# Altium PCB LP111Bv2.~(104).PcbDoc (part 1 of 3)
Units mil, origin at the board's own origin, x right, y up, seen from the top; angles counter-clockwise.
Board outline 3543.31 x 7480.32 mil, 4 copper layers (Top Layer, Signal Layer 1, Signal Layer 2, Bottom Layer), stack 40 mil thick; 284 components, 118 nets, 594 pads, 103 vias.
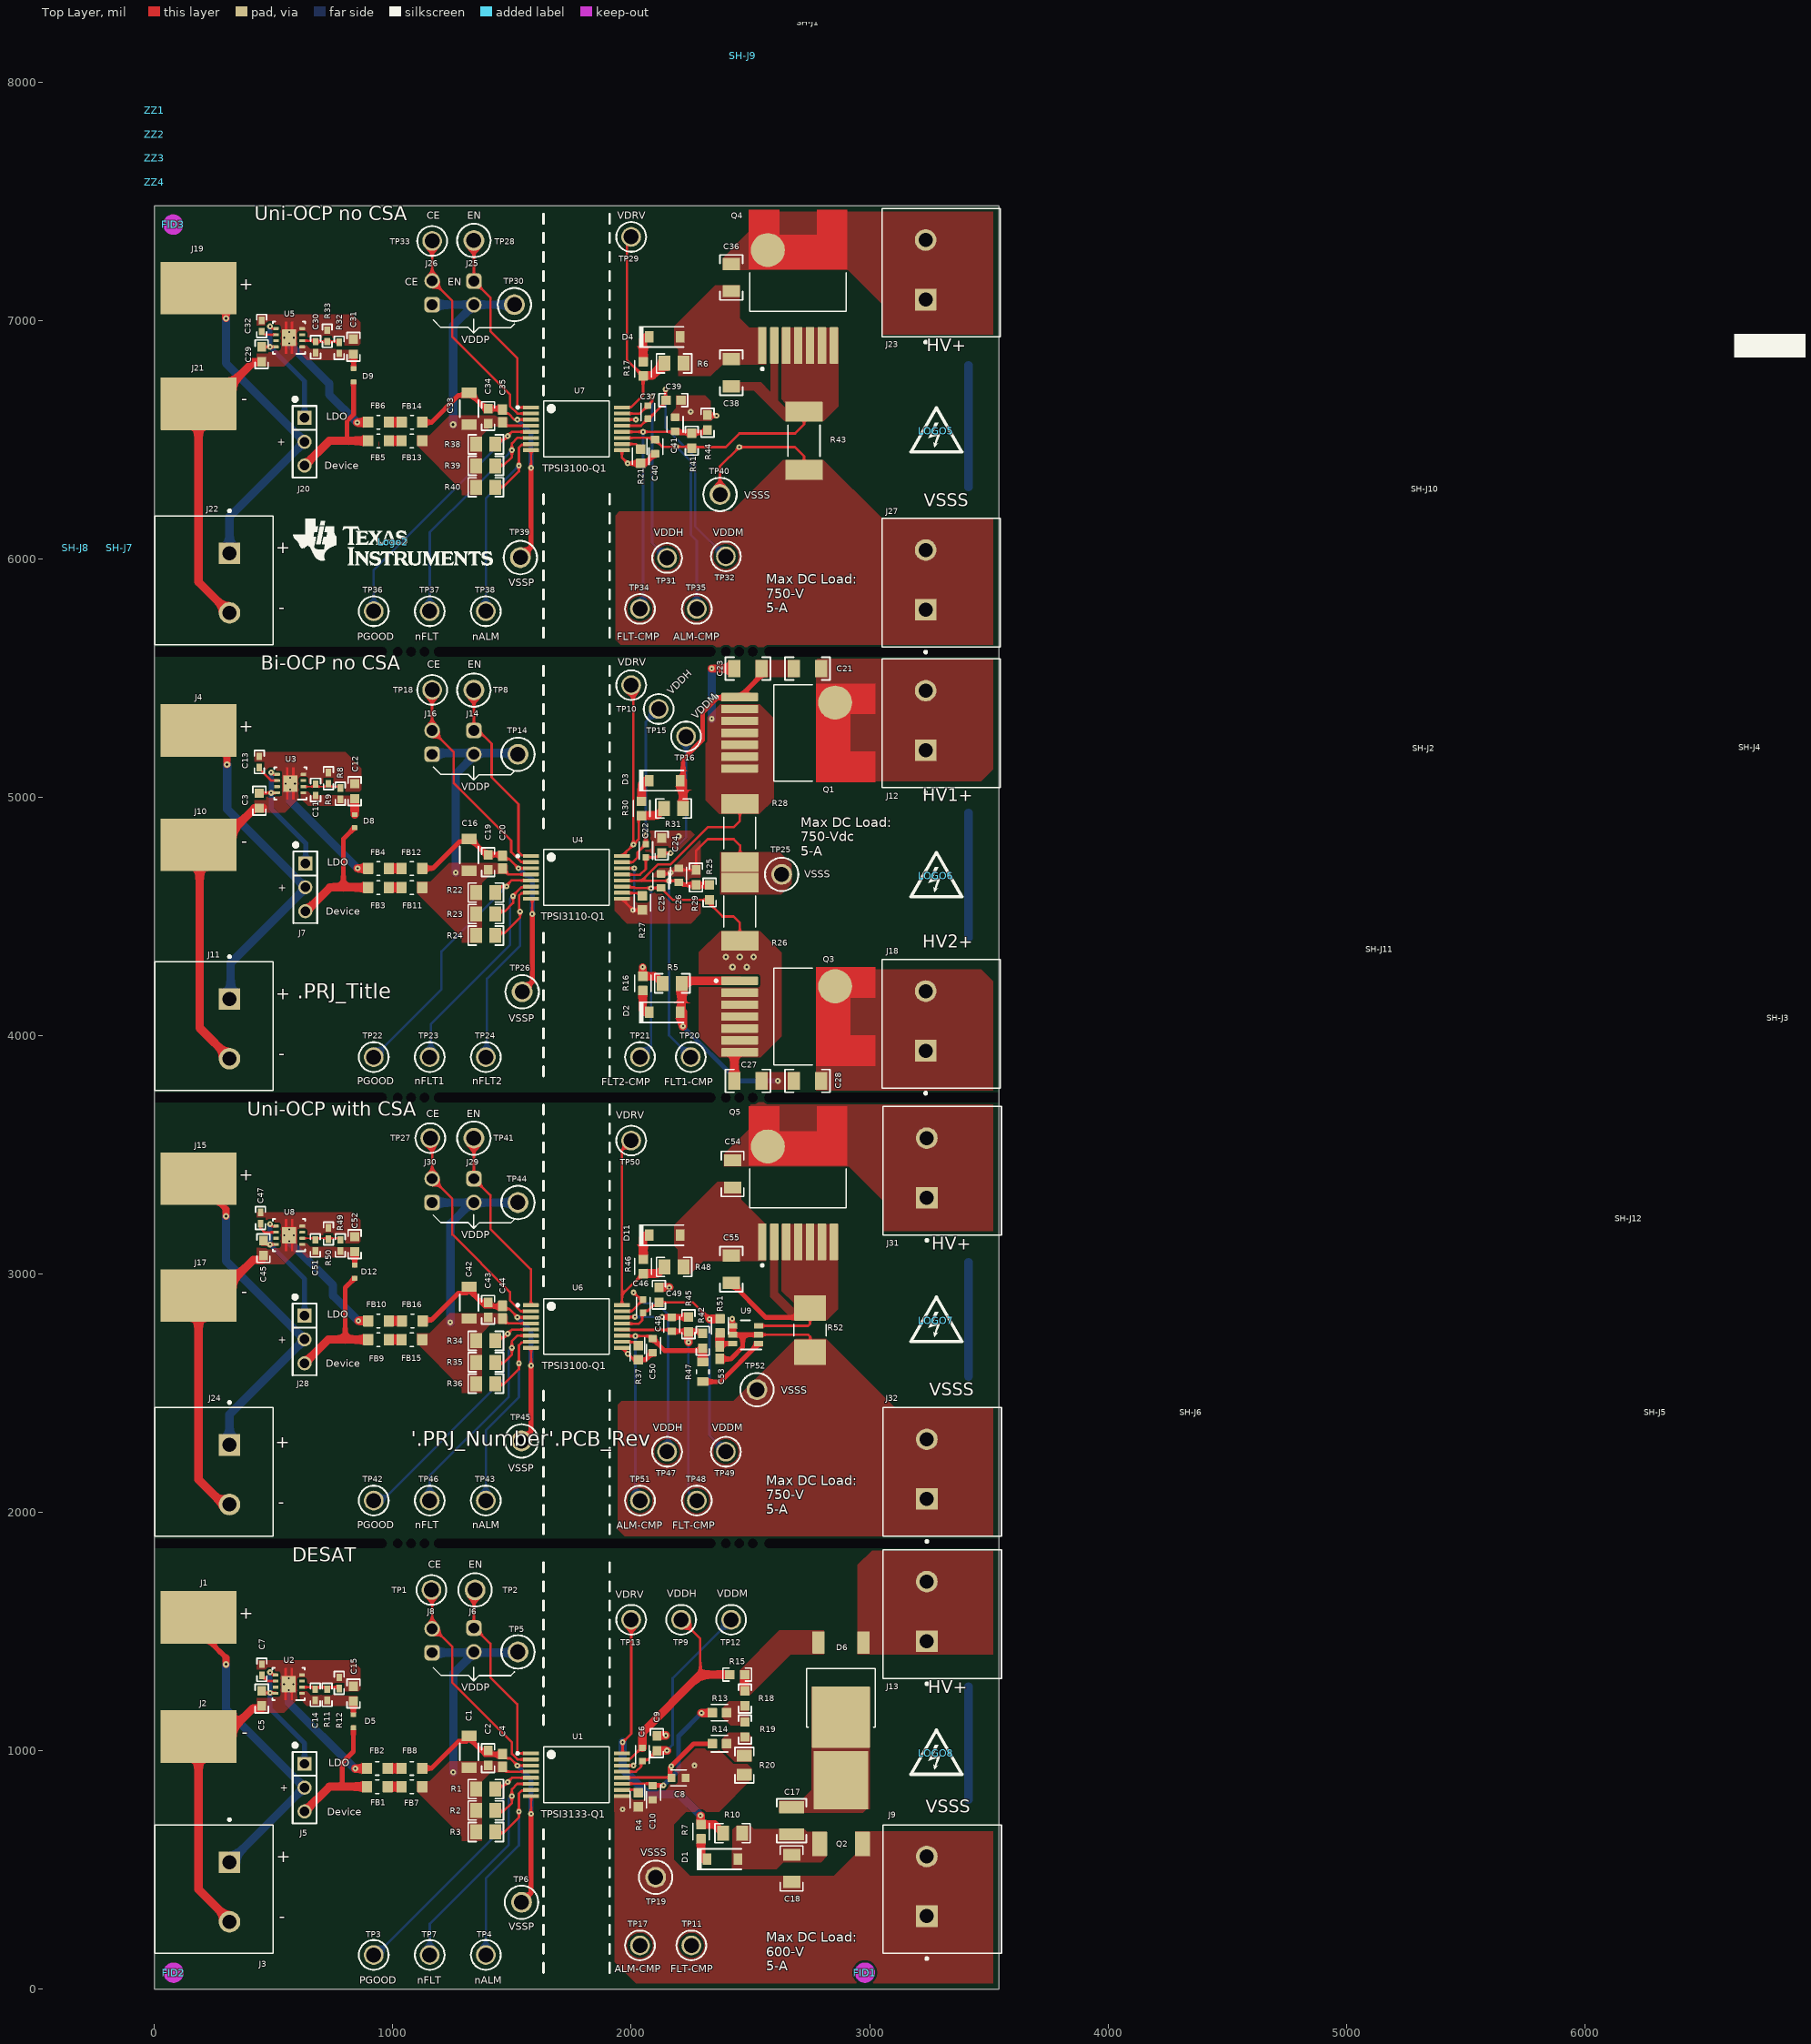
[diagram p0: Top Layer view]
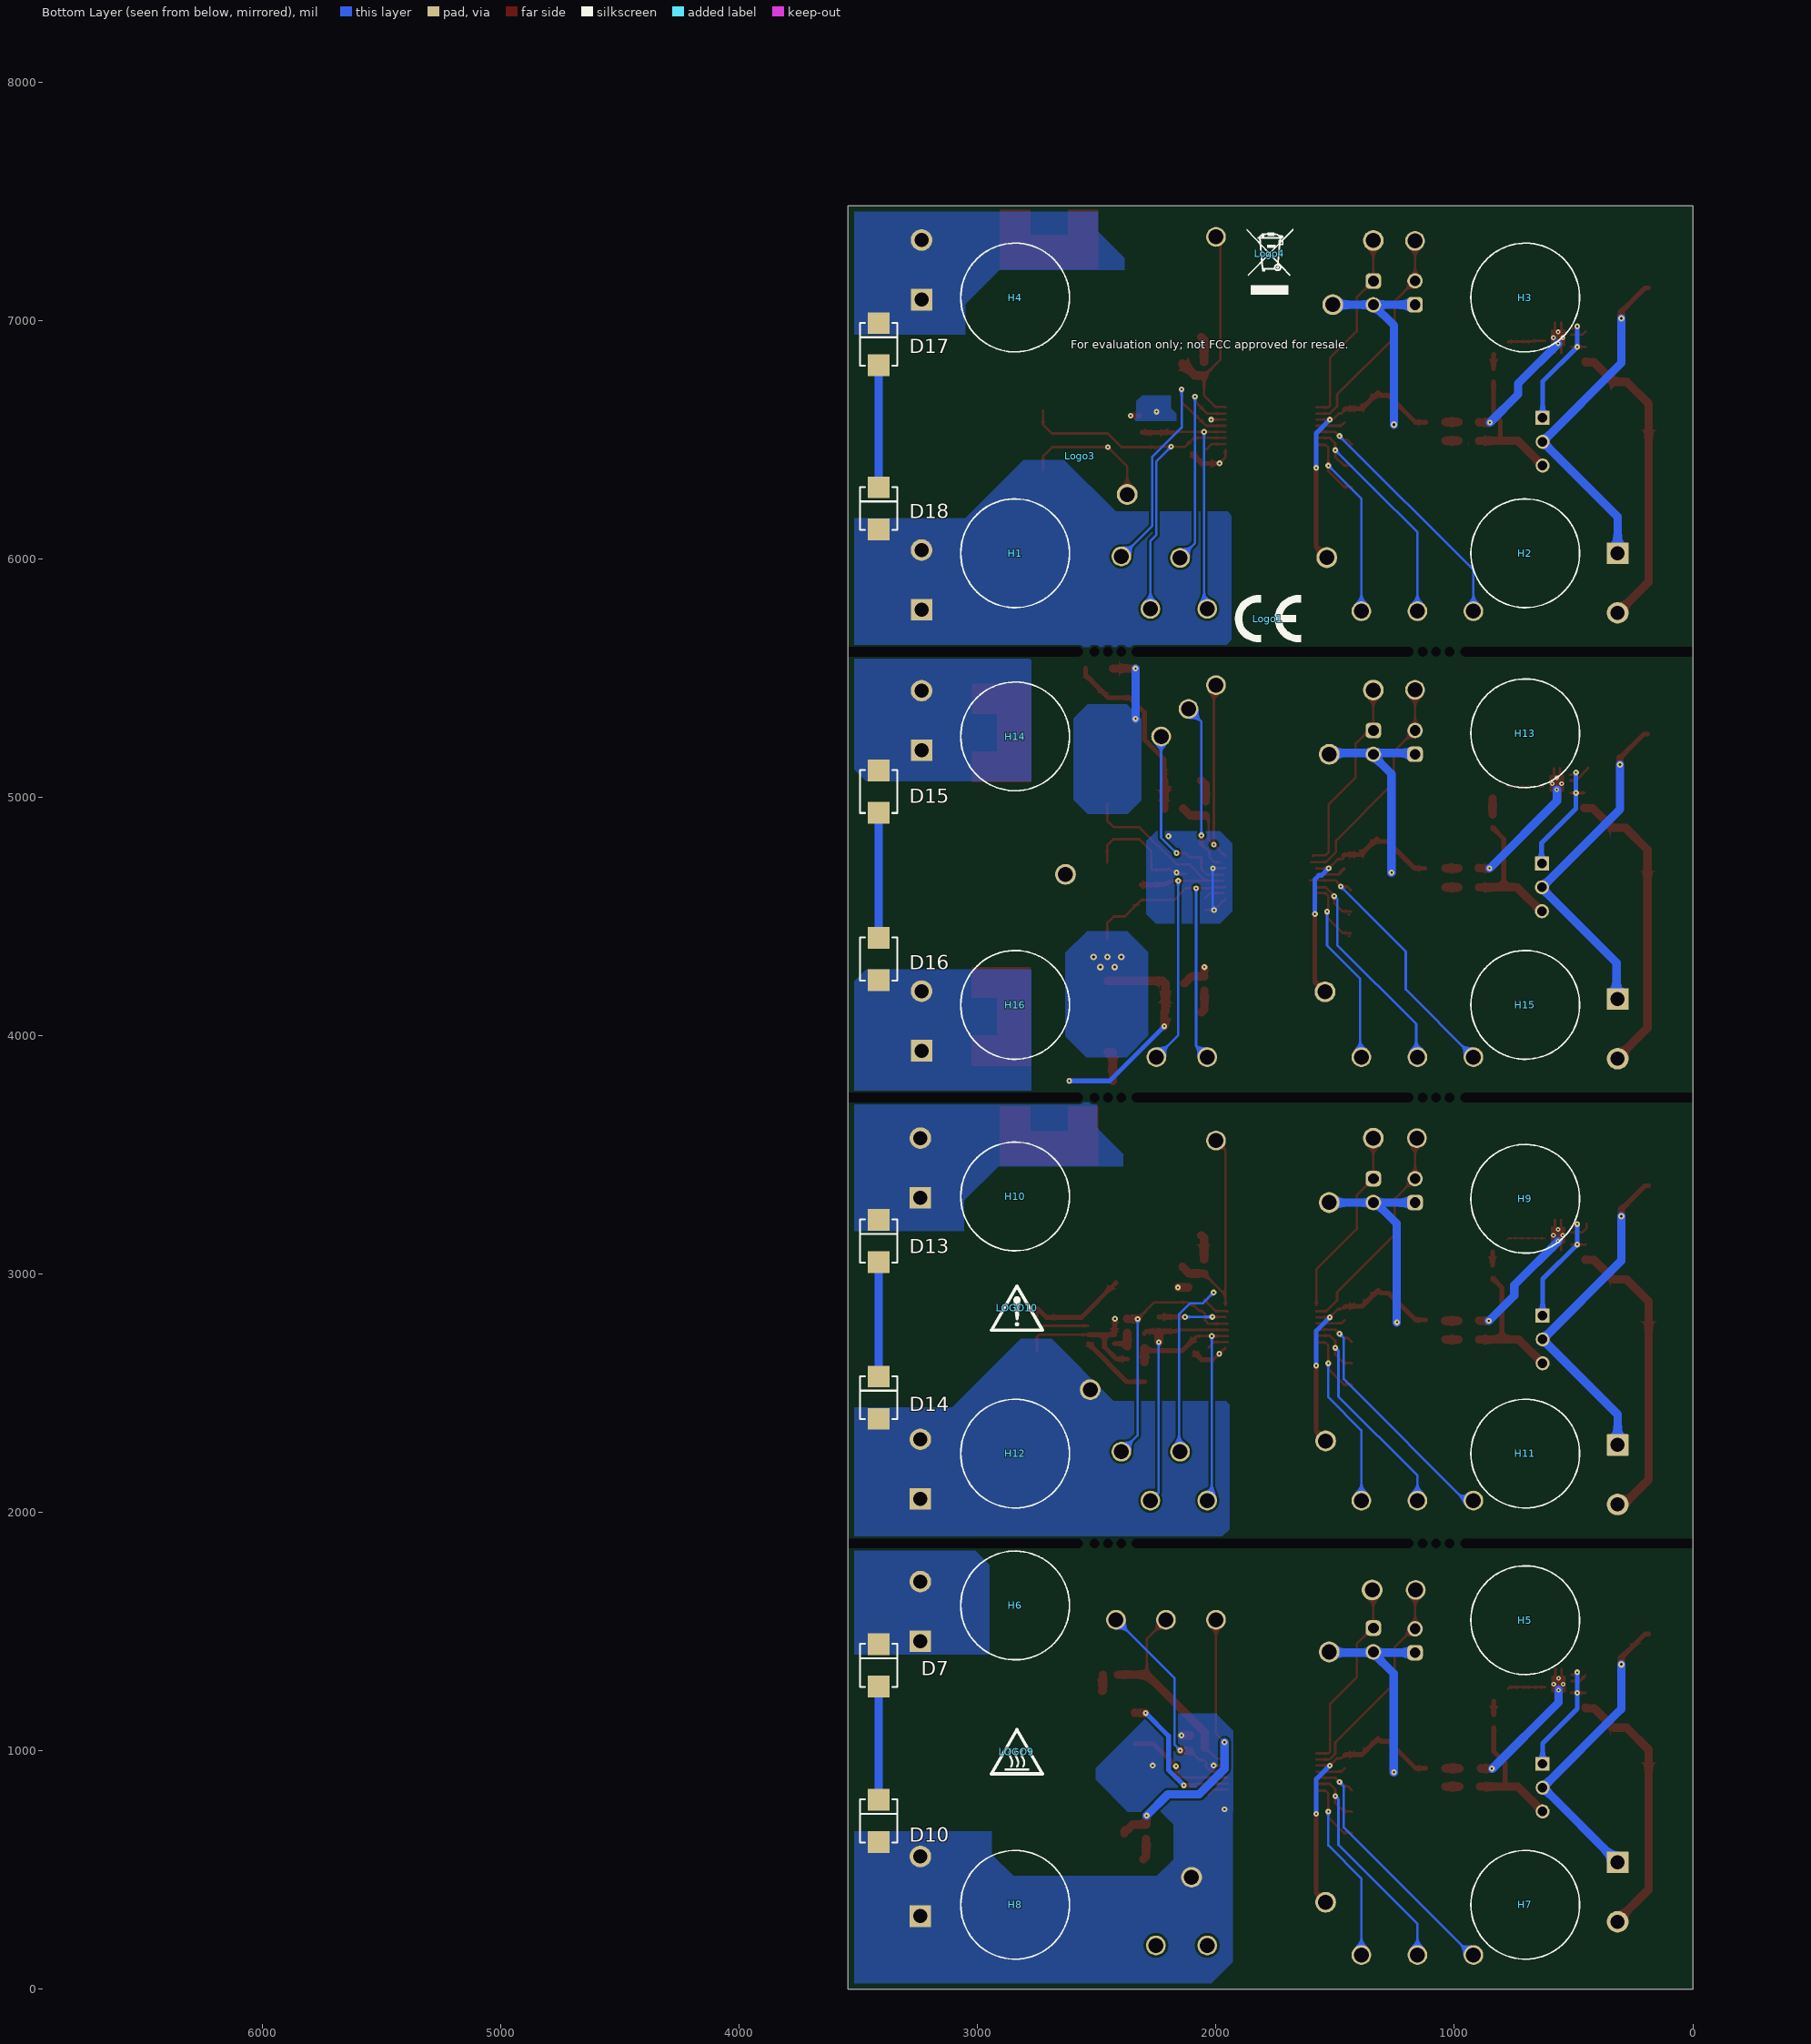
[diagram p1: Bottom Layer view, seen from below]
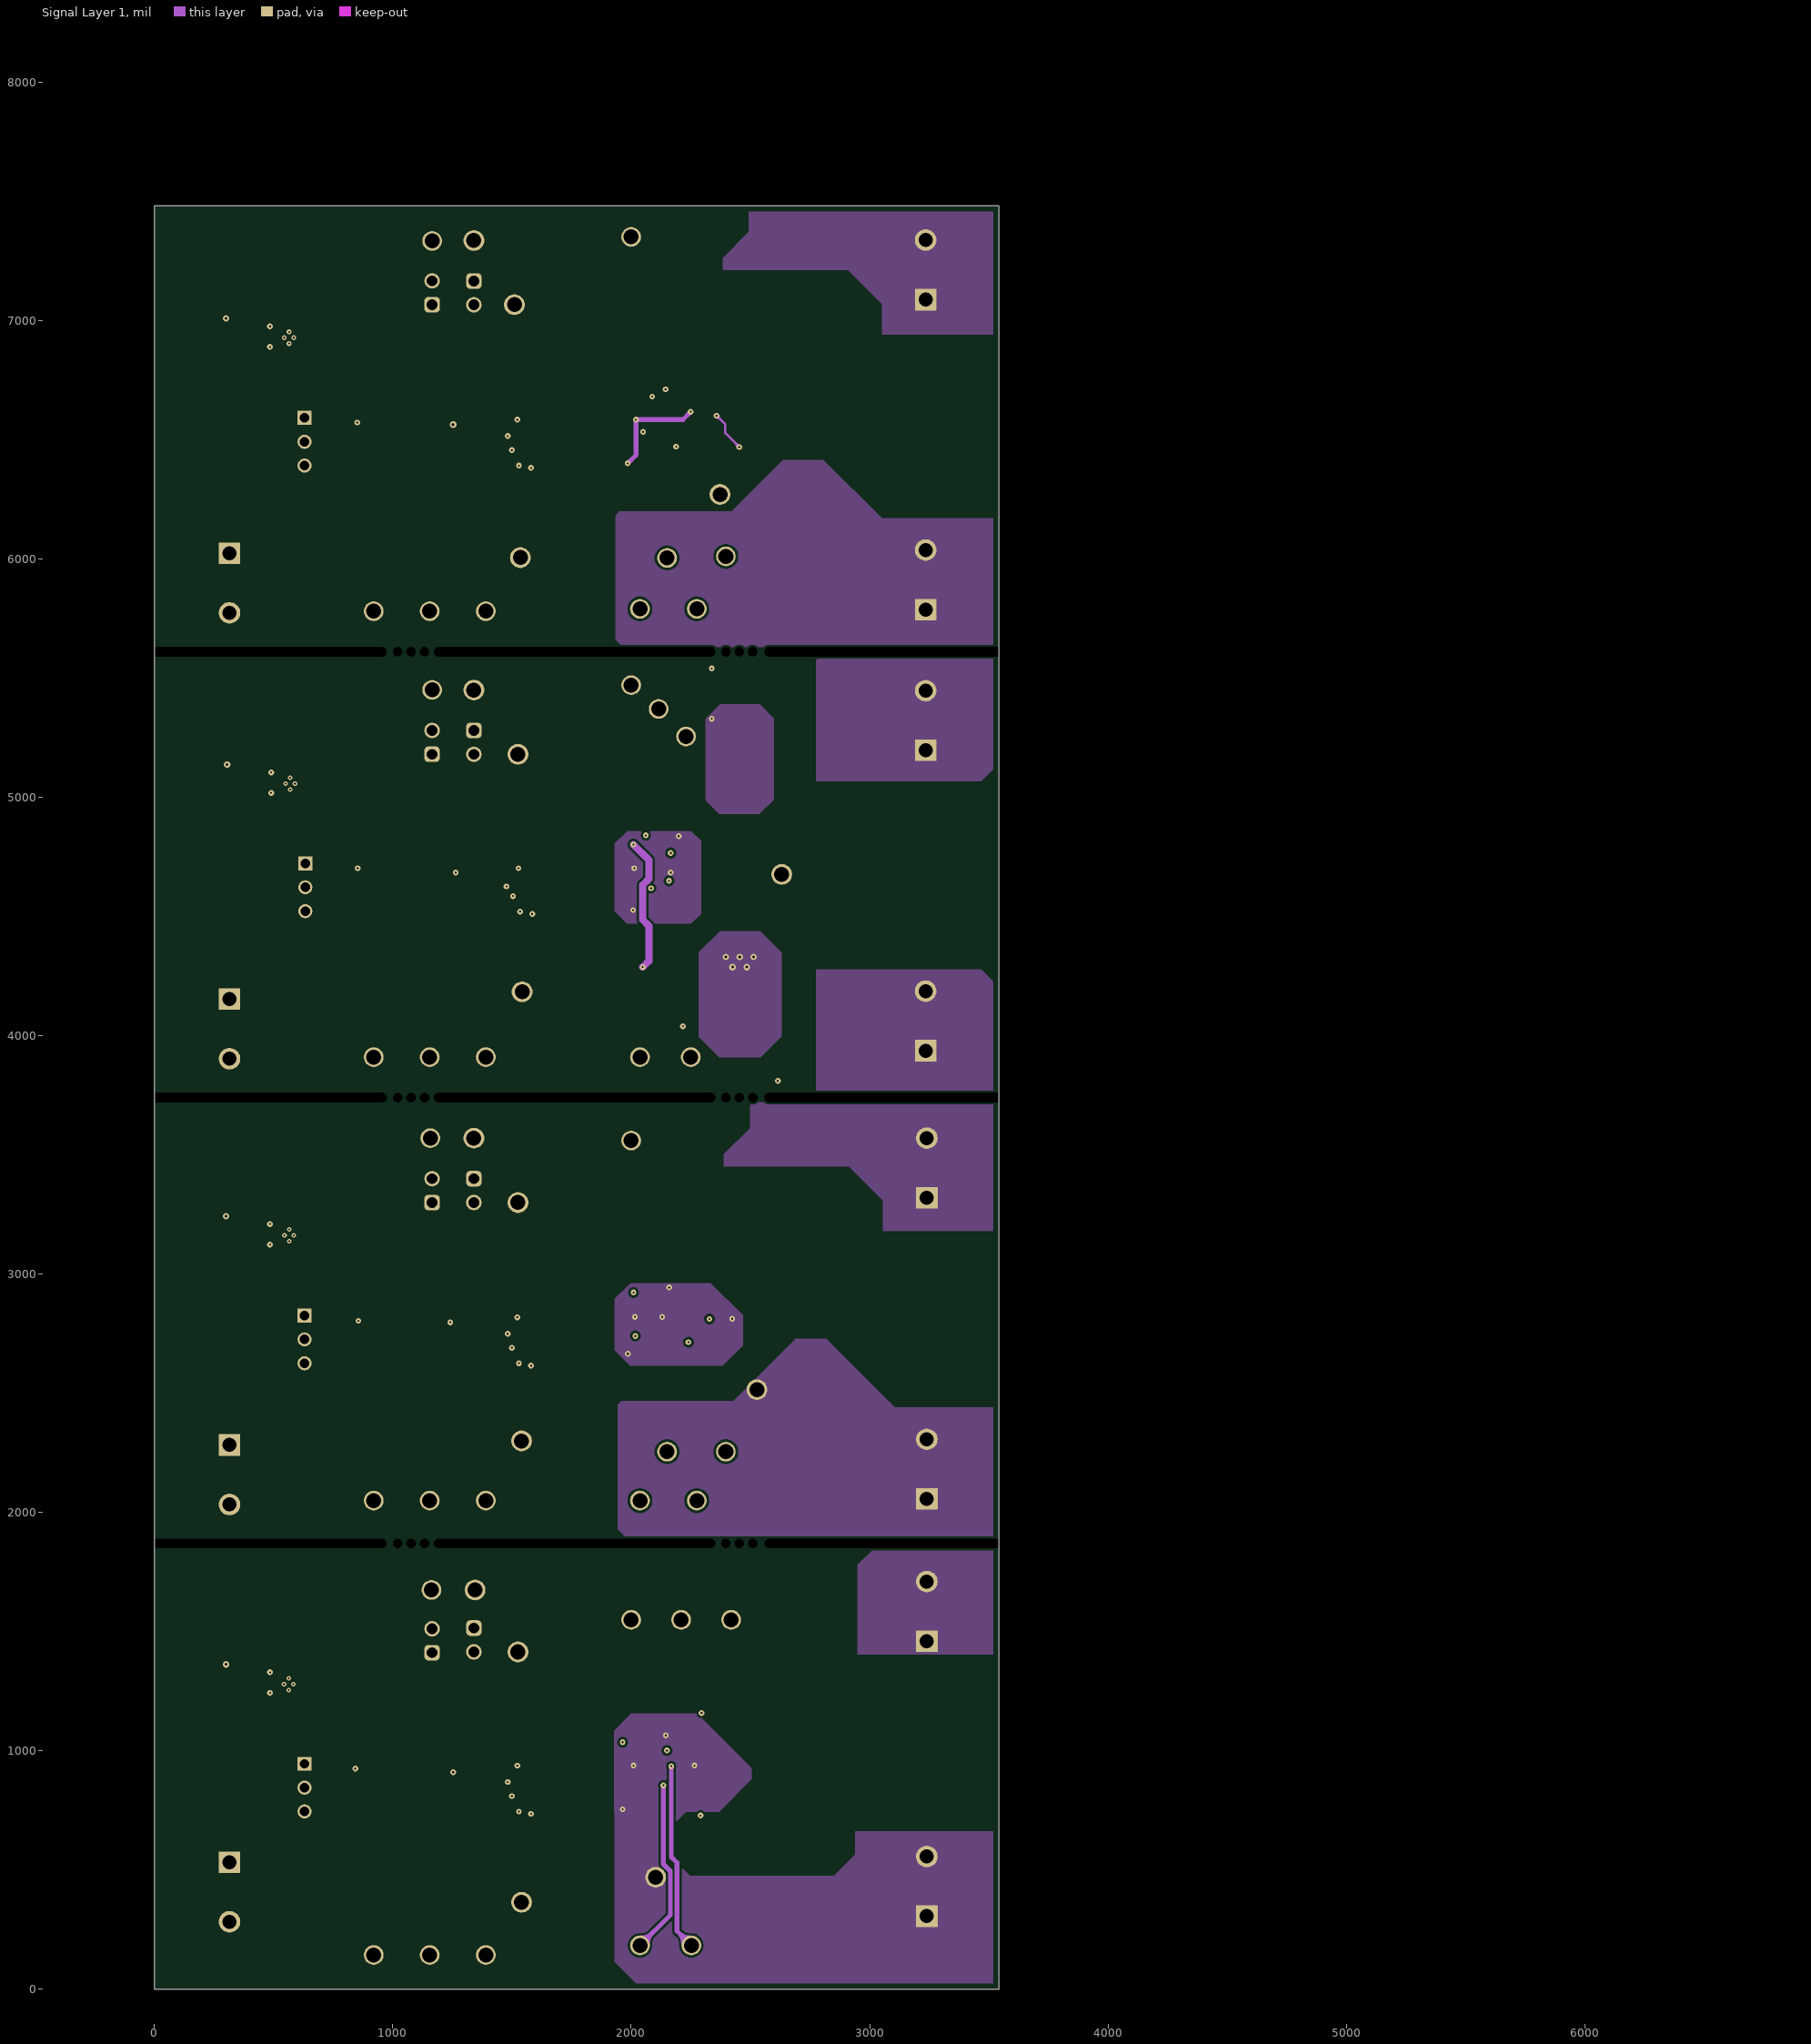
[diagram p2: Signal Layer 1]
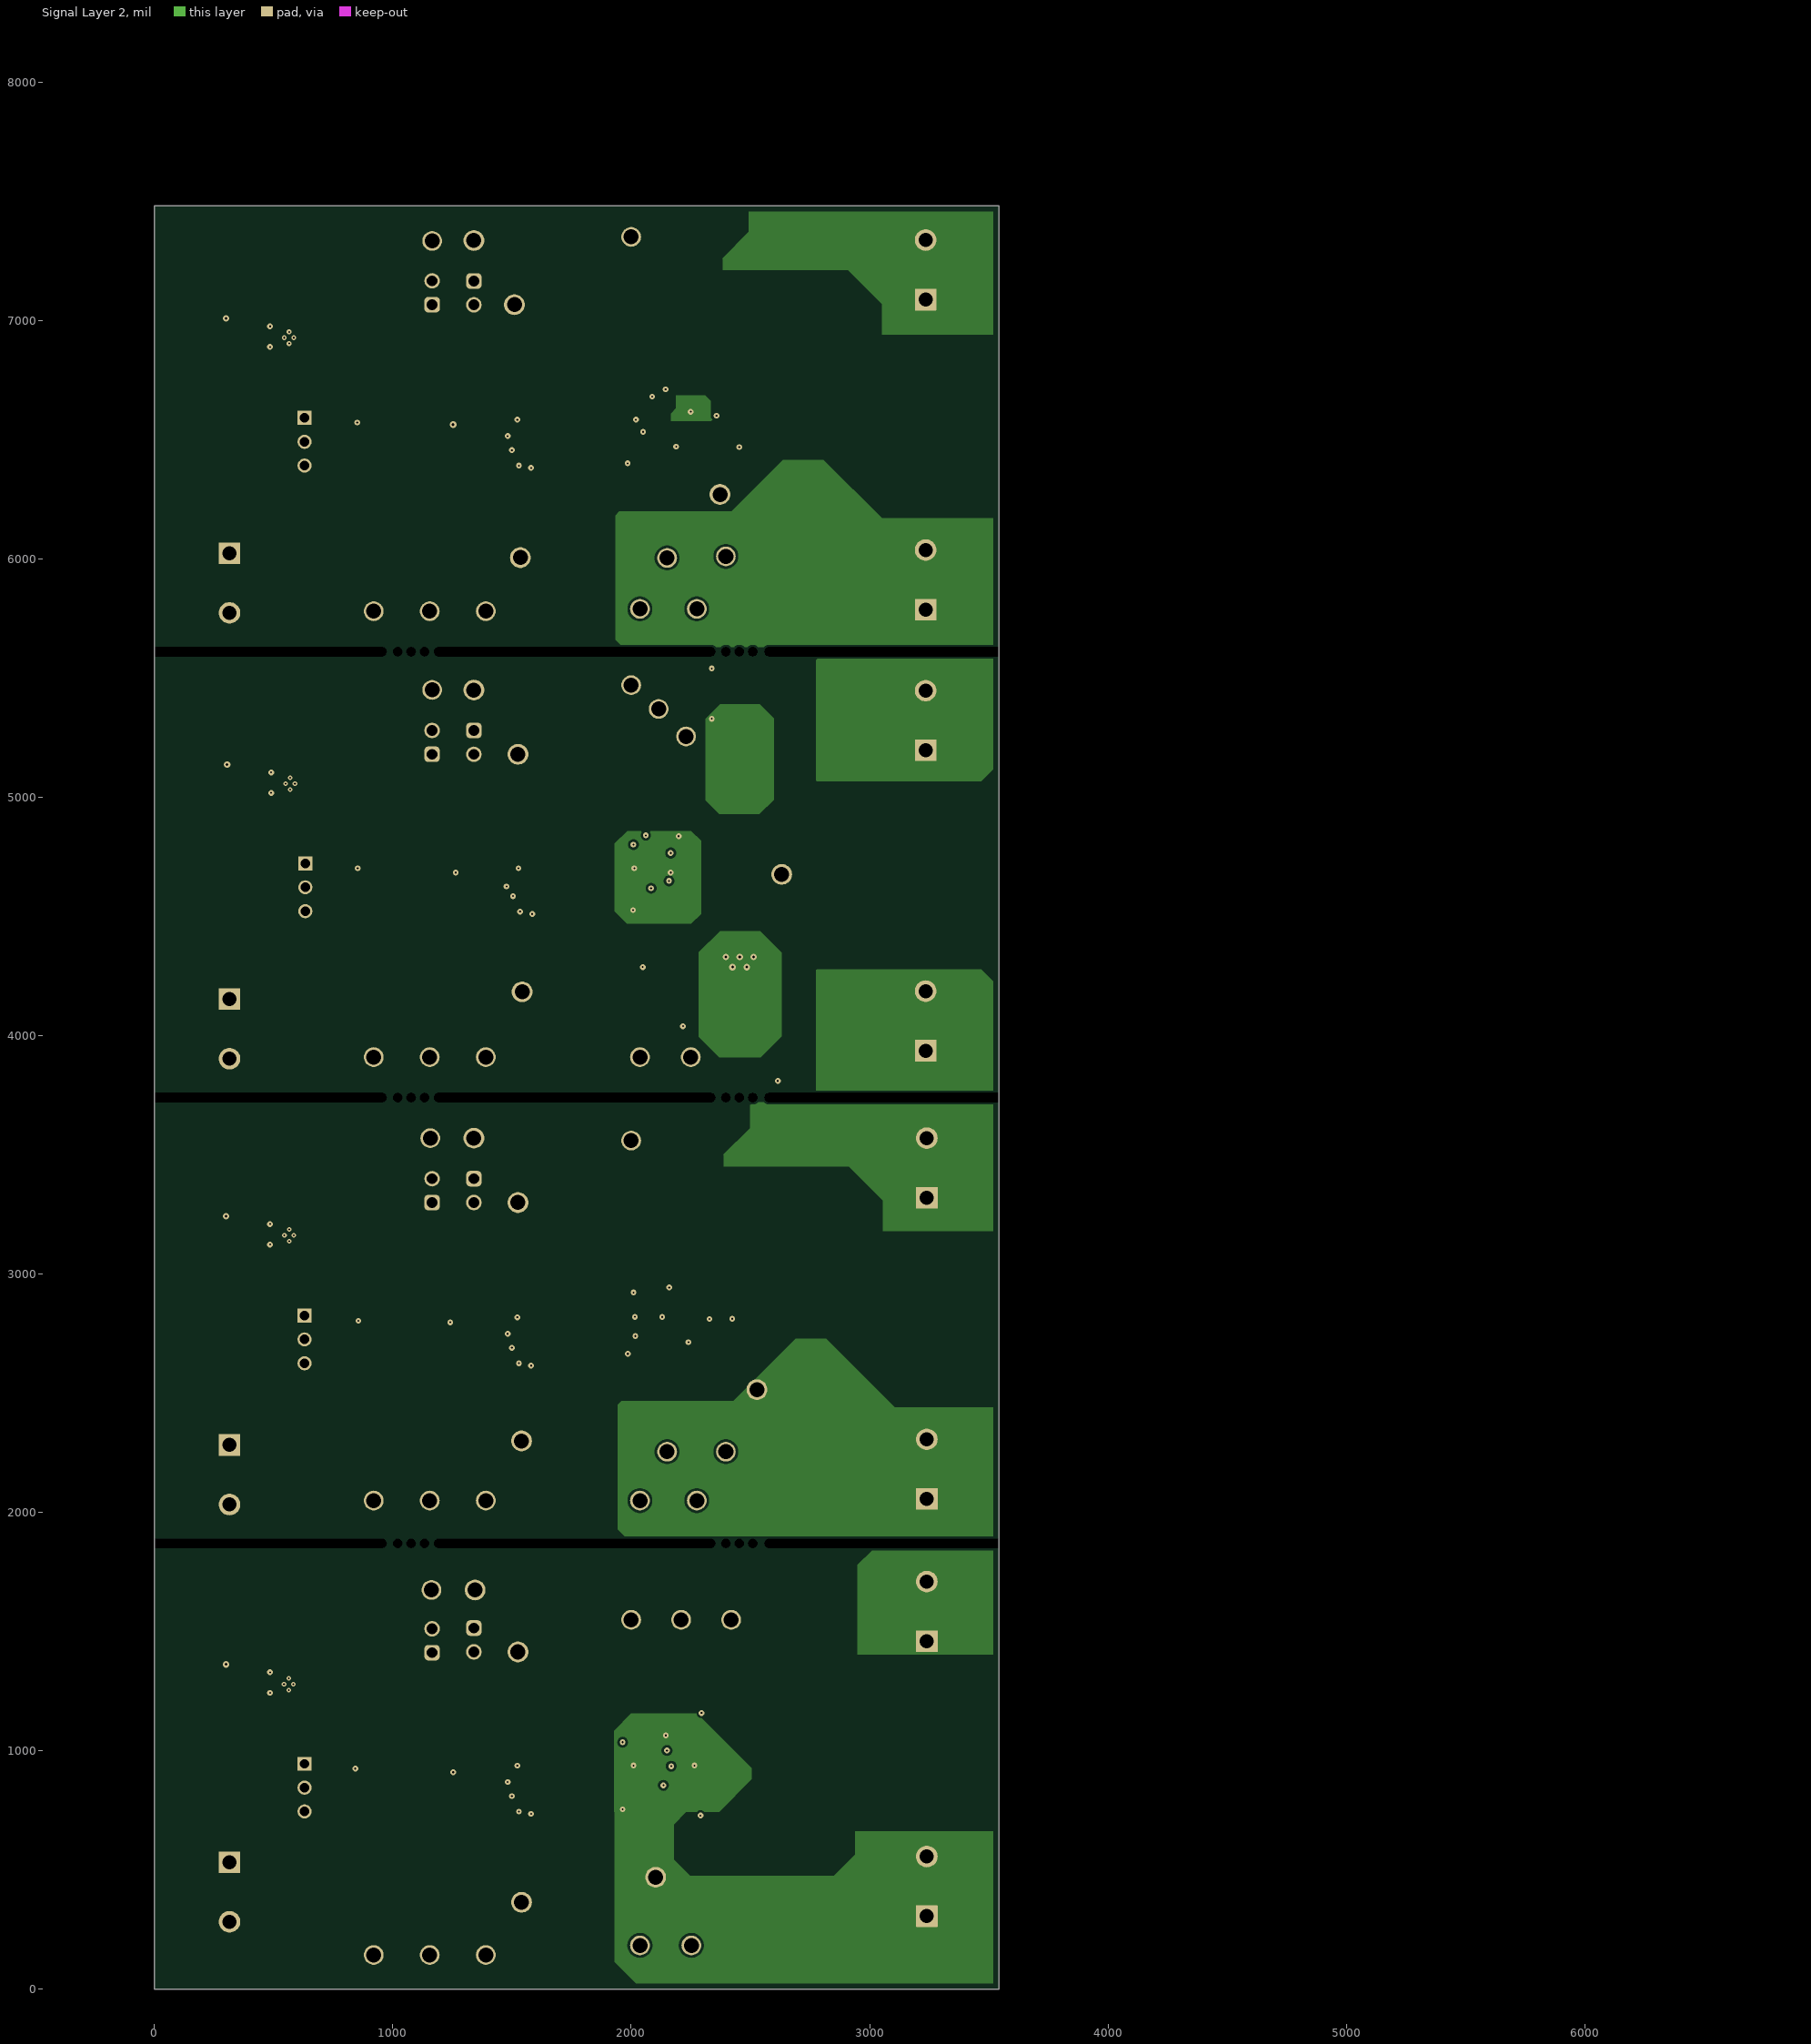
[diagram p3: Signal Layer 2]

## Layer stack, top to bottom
Top Solder: solder mask 0.4, Solder Resist, Dk 3.5
Top Layer: signal copper 2.8
Dielectric 1: prepreg 5, FR-4 High Tg, Dk 4.2
Signal Layer 1: signal copper 1.4
Dielectric 2: core 21.6, FR-4 High Tg, Dk 4.2
Signal Layer 2: signal copper 1.4
Dielectric 3: prepreg 5, FR-4 High Tg, Dk 4.2
Bottom Layer: signal copper 2.8
Bottom Solder: solder mask 0.4, Solder Resist, Dk 3.5

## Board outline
0,0 3543.31,0 3543.31,7480.32 0,7480.32

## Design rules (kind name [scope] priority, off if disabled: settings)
AcuteAngle [All] p1: minimum=4.50000000000000E+0001 checktracksonly=FALSE
AssemblyTestPointUsage [All] p1: valid=2
BoardOutlineClearance BoardOutlineClearance_MountingHoles [OnCopper and InComponentClass('Mounting Holes')] p1: gap=39.37 ignorepadtopadclearanceinfootprint=FALSE
BoardOutlineClearance BoardOutlineClearance_Poly [OnCopper and IsPoly] p2: gap=25 ignorepadtopadclearanceinfootprint=FALSE
BoardOutlineClearance [OnCopper and Not InComponentClass('Logo') and not InComponentClass('FiducialMark') and not InRegion(1000,500,4000,800) and not InPoly] p3: gap=40 ignorepadtopadclearanceinfootprint=FALSE
Clearance Clearance_Keepouts [((IsTrack Or IsArc) And Not InPoly) And IsFree and IsKeepOut vs ((IsTrack Or IsArc) And Not InPoly) And IsFree and IsKeepOut] p1: gap=0 ignorepadtopadclearanceinfootprint=FALSE
Clearance Clearance_Poly [InPolygon] p2: gap=10 ignorepadtopadclearanceinfootprint=TRUE
Clearance Clearance_FiducialMark [IsKeepOut and InComponentClass('FiducialMark') vs IsPad and InComponentClass('FiducialMark')] p3: gap=0 ignorepadtopadclearanceinfootprint=FALSE
Clearance [All] p4: gap=7.87 ignorepadtopadclearanceinfootprint=TRUE
ComponentClearance ComponentClearance_MountingHoles_FiducialMarks [InComponentClass('Mounting Holes') vs InComponentClass('FiducialMark')] p1: gap=50 collisioncheckmode=3 verticalgap=10 showdistances=FALSE
ComponentClearance ComponentClearance_Shunt [InComponentClass('Header') vs InComponentClass('Shunt')] p2: gap=0 collisioncheckmode=3 verticalgap=0 showdistances=FALSE
ComponentClearance ComponentClearance_Logo [InComponentClass('Logo')] p3: gap=30 collisioncheckmode=3 verticalgap=10 showdistances=FALSE
ComponentClearance ComponentClearance_ScrewToNut [(HasFootprint('NY PMS 440 0025 PH')) vs (HasFootprint('Keystone_1902C'))] p4: gap=5 collisioncheckmode=3 verticalgap=10 showdistances=FALSE
ComponentClearance ComponentClearance_MountingHoles [InComponentClass('Mounting Holes')] p5: gap=100 collisioncheckmode=3 verticalgap=100000 showdistances=FALSE
ComponentClearance ComponentClearance_SmallPassives [HasFootprint('0201*') or HasFootprint('0402*') or HasFootprint('0508') or HasFootprint('0603*') or HasFootprint('0612') or HasFootprint('0805*') or HasFootprint('0815*') or HasFootprint('0830*') or HasFootprint('1206*') or HasFootprint('1210*') or HasFootprint('1808*') or HasFootprint('1812*') or HasFootprint('1825*') or HasFootprint('2010*') or HasFootprint('2220*') or HasFootprint('2225*') or HasFootprint('2512*') or HasFootprint('2728*') or HasFootprint('3518*') vs HasFootprint('0201*') or HasFootprint('0402*') or HasFootprint('0508') or HasFootprint('0603*') or HasFootprint('0612') or HasFootprint('0805*') or HasFootprint('0815*') or HasFootprint('0830*') or HasFootprint('1206*') or HasFootprint('1210*') or HasFootprint('1808*') or HasFootprint('1812*') or HasFootprint('1825*') or HasFootprint('2010*') or HasFootprint('2220*') or HasFootprint('2225*') or HasFootprint('2512*') or HasFootprint('2728*') or HasFootprint('3518*')] p6: gap=14.96 collisioncheckmode=3 verticalgap=10 showdistances=FALSE
ComponentClearance ComponentClearance_THtoSMT [IsThruComponent vs IsSMTComponent] p7: gap=30 collisioncheckmode=3 verticalgap=30 showdistances=FALSE
ComponentClearance ComponentClearance_THtoTH [IsThruComponent vs IsThruComponent] p8: gap=20 collisioncheckmode=3 verticalgap=30 showdistances=FALSE
ComponentClearance [All] p9: gap=20 collisioncheckmode=3 verticalgap=10 showdistances=FALSE
DiffPairsRouting [All] p1: maxlimit=100 minlimit=10 mostfreqgap=10 toplayer_minwidth=15 toplayer_maxwidth=15 toplayer_prefwidth=15 midlayer1_minwidth=15 midlayer1_maxwidth=15 midlayer1_prefwidth=15 midlayer2_minwidth=15 midlayer2_maxwidth=15 midlayer2_prefwidth=15 bottomlayer_minwidth=15 bottomlayer_maxwidth=15 bottomlayer_prefwidth=15 maxuncoupledlength=1000
FabricationTestPointUsage TestPointUsage [All] p1: valid=2 allowmultiple=FALSE
FabricationTestpoint Testpoint [All] p1: side=3 testpointundercomponent=TRUE minsize=40 maxsize=100 preferedsize=60 minholesize=0 maxholesize=40 preferedholesize=32 testpointgrid=1 allowsidetop=TRUE allowsidebottom=TRUE usegrid=TRUE gridtolerance=0.01
FanoutControl Fanout_LCC [IsLCC] p1: bgadir=Out bgaviamode=Centered fanoutstyle=Auto fanoutdirection=Alternating viagrid=1 // Fanout_LCC (Default Rule)
FanoutControl Fanout_BGA [IsBGA] p2: bgadir=Out bgaviamode=Centered fanoutstyle=Auto fanoutdirection=Alternating viagrid=1 // Fanout_BGA (Default Rule)
FanoutControl Fanout_Default [All] p4: bgadir=Out bgaviamode=Centered fanoutstyle=Auto fanoutdirection=Alternating viagrid=1 // Fanout_Default (Default Rule)
FanoutControl Fanout_Small [(CompPinCount < 5)] p5: bgadir=Out bgaviamode=Centered fanoutstyle=Auto fanoutdirection=OutThenIn viagrid=1 // Fanout_Small (Default Rule)
HoleSize [All] p1: absolutevalues=TRUE maxlimit=251 minlimit=7.87 maxpercent=80.000 minpercent=20.000
MinimumAnnularRing MinimumAnnularRing_ThermalPadVias [IsVia and InAnyComponent] p1: minimumring=5.91
MinimumAnnularRing [All] p2: minimumring=7.87
MinimumSolderMaskSliver MinimumSolderMaskSliver_Logo [InComponentClass('Logo') vs InComponentClass('Logo')] p1: minsoldermaskwidth=0.7
MinimumSolderMaskSliver [All] p2: minsoldermaskwidth=3.94
PlaneConnect [All] p1: planeconnectstyle=Relief reliefexpansion=10 reliefentries=4 reliefconductorwidth=10 reliefairgap=10
PolygonConnect [All] p1: connectstyle=Direct reliefconductorwidth=10 reliefentries=4 polygonreliefangle="90 Angle" airgapwidth=10
RoutingVias ThermalPadVias [IsVia and InAnyComponent] p1: holewidth=7.87 width=19.68 viastyle="Through Hole" minholewidth=7.87 minwidth=19.68 maxholewidth=12.99 maxwidth=23.62
RoutingVias [All] p2: holewidth=16 width=34 viastyle="Through Hole" minholewidth=7.87 minwidth=24 maxholewidth=40 maxwidth=65
SilkToBoardRegionClearance [Not ((IsComment or IsDesignator) And (Hide <> 'False')) and not InRegion(1000,500,4000,800)] p1:
SilkToSilkClearance SilkToSilkClearance_Pb-FreeLogo [(HasFootprint('Pb-Free_Overlay_Medium') OR HasFootprint('Pb-Free_Overlay_Small')) vs (HasFootprint('Pb-Free_Overlay_Medium') OR HasFootprint('Pb-Free_Overlay_Small'))] p1: silktosilkclearance=0
SilkToSilkClearance [All] p2: silktosilkclearance=3.94
SilkToSolderMaskClearance SilkToComponentPadClearance [(IsPad or IsFill or IsRegion) and InAnycomponent] p1: minsilkscreentomaskgap=5 clearancetoexposedcopper=TRUE
SilkToSolderMaskClearance "Silk to Solder Mask Opening" [All] p2: minsilkscreentomaskgap=3.94 clearancetoexposedcopper=FALSE
SolderMaskExpansion [All] p1: expansion=1.97 istentingtop=FALSE
SupplyNets "Schematic Supply Nets_8" [InNet('1VSSS')] p1: voltage=0.000
SupplyNets "Schematic Supply Nets_7" [InNet('4VSSP')] p2: voltage=0.000
SupplyNets "Schematic Supply Nets_6" [InNet('4VDDH')] p3: voltage=0.000
SupplyNets "Schematic Supply Nets_5" [InNet('3VSSP')] p4: voltage=0.000
SupplyNets "Schematic Supply Nets_4" [InNet('4VSSS')] p5: voltage=0.000
SupplyNets "Schematic Supply Nets_3" [InNet('2VSSS')] p6: voltage=0.000
SupplyNets "Schematic Supply Nets_2" [InNet('2VSSP')] p7: voltage=0.000
SupplyNets "Schematic Supply Nets_1" [InNet('1VSSP')] p8: voltage=0.000
SupplyNets "Schematic Supply Nets" [InNet('3VSSS')] p9: voltage=0.000
UnRoutedNet [All] p1: checkbadconnections=TRUE
Width [All] p1: maxlimit=35 minlimit=6 preferedwidth=20 minimp=50.000000 maximp=50.000000 favimp=50.000000 checkconnectedcopper=TRUE
14 further rules are at their usual default settings.

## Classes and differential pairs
component class Shunt: SH-J1 SH-J2 SH-J3 SH-J4 SH-J5 SH-J6 SH-J7 SH-J8 SH-J9 SH-J10 SH-J11 SH-J12
component class Header: J5 J6 J7 J8 J14 J16 J20 J25 J26 J28 J29 J30
component class 4LP111B_DESAT.~(44): C1 C2 C4 C5 C6 C7 C8 C9 C10 C14 C15 C17 C18 D1 D5 D6 D7 D10 FB1 FB2 FB7 FB8 J1 J2 J3 J5 J6 J8 J9 J13 Q2 R1 R2 R3 R4 R7 R10 R11 R12 R13 R14 R15 R18 R19 R20 SH-J1 SH-J2 SH-J3 TP1 TP2 TP3 TP4 TP5 TP6 TP7 TP9 TP11 TP12 TP13 TP17 TP19 U1 U2
component class 3LP111B_Uni-OCP_CSA.~(35): C42 C43 C44 C45 C46 C47 C48 C49 C50 C51 C52 C53 C54 C55 D11 D12 D13 D14 FB9 FB10 FB15 FB16 J15 J17 J24 J28 J29 J30 J31 J32 Q5 R34 R35 R36 R37 R42 R45 R46 R47 R48 R49 R50 R51 R52 SH-J10 SH-J11 SH-J12 TP27 TP41 TP42 TP43 TP44 TP45 TP46 TP47 TP48 TP49 TP50 TP51 TP52 U6 U8 U9
component class 2LP111B_Bi-OCP_noCSA.~(38): C3 C11 C12 C13 C16 C19 C20 C21 C22 C23 C24 C25 C26 C27 C28 D2 D3 D8 D15 D16 FB3 FB4 FB11 FB12 J4 J7 J10 J11 J12 J14 J16 J18 Q1 Q3 R5 R8 R9 R16 R22 R23 R24 R25 R26 R27 R28 R29 R30 R31 SH-J4 SH-J5 SH-J6 TP8 TP10 TP14 TP15 TP16 TP18 TP20 TP21 TP22 TP23 TP24 TP25 TP26 U3 U4
component class 1LP111B_Uni-OCP_noCSA.~(35): C29 C30 C31 C32 C33 C34 C35 C36 C37 C38 C39 C40 C41 D4 D9 D17 D18 FB5 FB6 FB13 FB14 J19 J20 J21 J22 J23 J25 J26 J27 Q4 R6 R17 R21 R32 R33 R38 R39 R40 R41 R43 R44 SH-J7 SH-J8 SH-J9 TP28 TP29 TP30 TP31 TP32 TP33 TP34 TP35 TP36 TP37 TP38 TP39 TP40 U5 U7
component class Logo: Logo2
component class LP111A_Hardware: FID1 FID2 FID3 H1 H2 H3 H4 H5 H6 H7 H8 H9 H10 H11 H12 H13 H14 H15 H16 Logo1 Logo2 Logo3 Logo4 LOGO5 LOGO6 LOGO7 LOGO8 LOGO9 LOGO10 ZZ1 ZZ2 ZZ3 ZZ4
component class FiducialMark: FID1 FID2 FID3
component class AssemblyNote: ZZ1 ZZ2 ZZ3 ZZ4

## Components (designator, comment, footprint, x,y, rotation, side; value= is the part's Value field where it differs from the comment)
C1 "C1206C106J3RACAUTO" 1206_180 1320,996.6 r90 top value=10uF
C2 "GCM188R71E105KA64D" 0603 1400,970 r90 top value=1uF
C3 "GRT188R61E106ME13D" 0603 440,4985 r270 top value=10uF
C4 "C0603R104K5RAC" FP-C0603R104K5RAC_0603-IPC_B 1460,960 r270 top
C5 "GRT188R61E106ME13D" 0603 450,1220 r270 top value=10uF
C6 "CGA3E3X7R1E334K080AB" FP-CGA3E3X7R1E334K080AB_0603-MFG 2046.79,984.72 r270 top value=330nF
C7 "GRM155R71E103KA01D" 0402 450.62,1340.04 r90 top value=0.01uF
C8 "CC0603KRX7R7BB102" FP-CC0603KRX7R7BB102_0603-MFG 2198.67,886.99 r180 top value=1nF
C9 "GCM188R71E105KA64D" 0603 2107.72,1032.03 r270 top value=1uF
C10 "CC0603KRX7R7BB102" FP-CC0603KRX7R7BB102_0603-MFG 2090,825 r90 top value=1nF
C11 "GRM155R71E103KA01D" 0402 676.34,5030.79 r90 top value=0.01uF
C12 "GRT188R61E106ME13D" 0603 840,5025 r90 top value=10uF
C13 "GRM155R71E103KA01D" 0402 440,5147.76 r90 top value=0.01uF
C14 "GRM155R71E103KA01D" 0402 674.83,1235.04 r90 top value=0.01uF
C15 "GRT188R61E106ME13D" 0603 835,1240 r90 top value=10uF
C16 "C1206C106J3RACAUTO" 1206_180 1320,4758.7 r90 top value=10uF
C17 "GRM32QR72J223KW01L" 1210_150 2672.92,707.14 r270 top value=0.022uF
C18 "GRM31A7U3A101JW31D" 1206 2672.92,507.09 r90 top value=100pF
C19 "GCM188R71E105KA64D" 0603 1400,4727.2 r90 top value=1uF
C20 "C0603R104K5RAC" FP-C0603R104K5RAC_0603-IPC_B 1460,4727.2 r270 top
C21 "GRM31A7U3A680JW31D" 1206 2740,5540 r180 top value=68pF
C22 "CGA3E3X7R1E334K080AB" FP-CGA3E3X7R1E334K080AB_0603-MFG 2061.28,4775.72 r270 top value=330nF
C23 "GRM31A7U3A101JW31D" 1206 2490,5540 r0 top value=100pF
C24 "GCM188R71E105KA64D" 0603 2127.72,4797.34 r270 top value=1uF
C25 "CC0603KRX7R7BB102" FP-CC0603KRX7R7BB102_0603-MFG 2125,4649.06 r270 top value=1nF
C26 "CC0603KRX7R7BB102" FP-CC0603KRX7R7BB102_0603-MFG 2199.2,4672.22 r270 top value=1nF
C27 "GRM31A7U3A101JW31D" 1206 2490,3810 r0 top value=100pF
C28 "GRM31A7U3A680JW31D" 1206 2740,3810 r180 top value=68pF
C29 "GRT188R61E106ME13D" 0603 449.96,6857.98 r270 top value=10uF
C30 "GRM155R71E103KA01D" 0402 676.34,6887.51 r90 top value=0.01uF
C31 "GRT188R61E106ME13D" 0603 835,6889.48 r90 top value=10uF
C32 "GRM155R71E103KA01D" 0402 449.96,6976.58 r90 top value=0.01uF
C33 "C1206C106J3RACAUTO" 1206_180 1320,6630 r90 top value=10uF
C34 "GCM188R71E105KA64D" 0603 1400,6598.5 r90 top value=1uF
C35 "C0603R104K5RAC" FP-C0603R104K5RAC_0603-IPC_B 1460,6599.25 r270 top
C36 "GRM31A7U3A680JW31D" 1206 2420,7180 r270 top value=68pF
C37 "CGA3E3X7R1E334K080AB" FP-CGA3E3X7R1E334K080AB_0603-MFG 2070,6615 r270 top value=330nF
C38 "GRM31A7U3A101JW31D" 1206 2420,6780 r90 top value=100pF
C39 "GCM188R71E105KA64D" 0603 2177.05,6665.43 r180 top value=1uF
C40 "CC0603KRX7R7BB102" FP-CC0603KRX7R7BB102_0603-MFG 2100,6470 r90 top value=1nF
C41 "CC0603KRX7R7BB102" FP-CC0603KRX7R7BB102_0603-MFG 2184.18,6563.94 r270 top value=1nF
C42 "C1206C106J3RACAUTO" 1206_180 1320,2880 r90 top value=10uF
C43 "GCM188R71E105KA64D" 0603 1400,2850 r90 top value=1uF
C44 "C0603R104K5RAC" FP-C0603R104K5RAC_0603-IPC_B 1460,2840 r270 top
C45 "GRT188R61E106ME13D" 0603 457.52,3108.71 r270 top value=10uF
C46 "CGA3E3X7R1E334K080AB" FP-CGA3E3X7R1E334K080AB_0603-MFG 2050.01,2865.07 r270 top value=330nF
C47 "GRM155R71E103KA01D" 0402 445,3235 r90 top value=0.01uF
C48 "CC0603KRX7R7BB102" FP-CC0603KRX7R7BB102_0603-MFG 2170,2789.06 r270 top value=1nF
C49 "GCM188R71E105KA64D" 0603 2116,2912.86 r270 top value=1uF
C50 "CC0603KRX7R7BB102" FP-CC0603KRX7R7BB102_0603-MFG 2090,2700 r90 top value=1nF
C51 "GRM155R71E103KA01D" 0402 675,3120 r90 top value=0.01uF
C52 "GRT188R61E106ME13D" 0603 840,3125 r90 top value=10uF
C53 "C0603R104K5RAC" FP-C0603R104K5RAC_0603-IPC_B 2371.34,2670.47 r270 top
C54 "GRM31A7U3A680JW31D" 1206 2425,3420 r270 top value=68pF
C55 "GRM31A7U3A101JW31D" 1206 2420,3020 r90 top value=100pF
D1 "MBR0540T1G" SOD-123 2383.1,546.14 r0 top value=40V
D2 "MBR0540T1G" SOD-123 2140.02,4097.76 r0 top value=40V
D3 "MBR0540T1G" SOD-123 2140.02,5069.55 r0 top value=40V
D4 "MBR0540T1G" SOD-123 2140.02,6930.32 r0 top value=40V
D5 "PMEG6002EB,115" FP-PMEG6002EB,115_SOD523-MFG 835,1124.78 r90 top
D6 "C3D03060E" FP-C3D03060E_TO-252-2-MFG 2880,1257.5 r180 top
D7 "824520402" WE-TVSP_DO-214AA_Unidirectional 3415,1358.58 r270 bottom
D8 "PMEG6002EB,115" FP-PMEG6002EB,115_SOD523-MFG 840,4900 r90 top
D9 "PMEG6002EB,115" FP-PMEG6002EB,115_SOD523-MFG 835.46,6770 r90 top
D10 "824520402" WE-TVSP_DO-214AA_Unidirectional 3415,706.42 r270 bottom
D11 "MBR0540T1G" SOD-123 2140.02,3162.91 r0 top value=40V
D12 "PMEG6002EB,115" FP-PMEG6002EB,115_SOD523-MFG 840,3010 r90 top
D13 "824520402" WE-TVSP_DO-214AA_Unidirectional 3415,3138.58 r270 bottom
D14 "824520402" WE-TVSP_DO-214AA_Unidirectional 3415,2481.42 r270 bottom
D15 "824521402" WE-TVSP_DO-214AA_Bidirectional 53415,55023.58 r90 bottom
D16 "824521402" WE-TVSP_DO-214AA_Bidirectional 53415,54321.42 r90 bottom
D17 "824520402" WE-TVSP_DO-214AA_Unidirectional 3415,6900 r270 bottom
D18 "824520402" WE-TVSP_DO-214AA_Unidirectional 3415,6211.42 r270 bottom
FB1 "BBBK00201209252Y00" FP-BBBK00201209252Y00_0805-MFG 935,850 r0 top
FB2 "BBBK00201209252Y00" FP-BBBK00201209252Y00_0805-MFG 935,926.56 r0 top
FB3 "BBBK00201209252Y00" FP-BBBK00201209252Y00_0805-MFG 940,4621.56 r0 top
FB4 "BBBK00201209252Y00" FP-BBBK00201209252Y00_0805-MFG 940,4701.56 r0 top
FB5 "BBBK00201209252Y00" FP-BBBK00201209252Y00_0805-MFG 940,6495 r0 top
FB6 "BBBK00201209252Y00" FP-BBBK00201209252Y00_0805-MFG 940,6573.22 r0 top
FB7 "BBBK00201209252Y00" FP-BBBK00201209252Y00_0805-MFG 1080,850 r0 top
FB8 "BBBK00201209252Y00" FP-BBBK00201209252Y00_0805-MFG 1080,926.56 r0 top
FB9 "BBBK00201209252Y00" FP-BBBK00201209252Y00_0805-MFG 940,2725 r0 top
FB10 "BBBK00201209252Y00" FP-BBBK00201209252Y00_0805-MFG 940,2803.53 r0 top
FB11 "BBBK00201209252Y00" FP-BBBK00201209252Y00_0805-MFG 1080,4621.56 r0 top
FB12 "BBBK00201209252Y00" FP-BBBK00201209252Y00_0805-MFG 1080,4701.56 r0 top
FB13 "BBBK00201209252Y00" FP-BBBK00201209252Y00_0805-MFG 1080,6495 r0 top
FB14 "BBBK00201209252Y00" FP-BBBK00201209252Y00_0805-MFG 1080.46,6573.22 r0 top
FB15 "BBBK00201209252Y00" FP-BBBK00201209252Y00_0805-MFG 1080,2725 r0 top
FB16 "BBBK00201209252Y00" FP-BBBK00201209252Y00_0805-MFG 1081.97,2803.53 r0 top
FID1 "Fiducial" Fiducial10-20 2980,70 r0 top
FID2 "Fiducial" Fiducial10-20 80,70 r0 top
FID3 "Fiducial" Fiducial10-20 78.74,7401.57 r0 top
H1 "SJ-5303 (CLEAR)" Bumpon_SJ5003Transparent 2842.52,6023.24 r180 bottom
H2 "SJ-5303 (CLEAR)" Bumpon_SJ5003Transparent 702.5,6023.24 r180 bottom
H3 "SJ-5303 (CLEAR)" Bumpon_SJ5003Transparent 702.5,7095.82 r180 bottom
H4 "SJ-5303 (CLEAR)" Bumpon_SJ5003Transparent 2842.52,7095.82 r180 bottom
H5 "SJ-5303 (CLEAR)" Bumpon_SJ5003Transparent 702.5,1548.19 r180 bottom
H6 "SJ-5303 (CLEAR)" Bumpon_SJ5003Transparent 2842.52,1610 r180 bottom
H7 "SJ-5303 (CLEAR)" Bumpon_SJ5003Transparent 702.5,354.36 r180 bottom
H8 "SJ-5303 (CLEAR)" Bumpon_SJ5003Transparent 2842.52,354.36 r180 bottom
H9 "SJ-5303 (CLEAR)" Bumpon_SJ5003Transparent 702.5,3315.55 r180 bottom
H10 "SJ-5303 (CLEAR)" Bumpon_SJ5003Transparent 2842.52,3325.51 r180 bottom
H11 "SJ-5303 (CLEAR)" Bumpon_SJ5003Transparent 702.5,2246.81 r180 bottom
H12 "SJ-5303 (CLEAR)" Bumpon_SJ5003Transparent 2842.52,2246.81 r180 bottom
H13 "SJ-5303 (CLEAR)" Bumpon_SJ5003Transparent 702.5,5268.19 r180 bottom
H14 "SJ-5303 (CLEAR)" Bumpon_SJ5003Transparent 2842.52,5255 r180 bottom
H15 "SJ-5303 (CLEAR)" Bumpon_SJ5003Transparent 702.5,4129.06 r180 bottom
H16 "SJ-5303 (CLEAR)" Bumpon_SJ5003Transparent 2842.52,4129.06 r180 bottom
J1 "108-0902-001" Cinch_108-0902-001 0,1560 r0 top
J2 "108-0903-001" Cinch_108-0903-001 0,1060 r0 top
J3 "691250610002" FP-691250610002_CONN_TERM_BLOCK2-MFG 250,420 r270 top
J4 "108-0902-001" Cinch_108-0902-001 0,5280 r0 top
J5 "PEC03SAAN" CONN_PEC03SAAN 629.87,845.72 r270 top
J6 "61300211121" WURTH_61300211121 1340,1465.18 r270 top
J7 "PEC03SAAN" CONN_PEC03SAAN 632.8,4622.06 r270 top
J8 "61300211121" WURTH_61300211121 1164.81,1462 r90 top
J9 "691250610002" FP-691250610002_CONN_TERM_BLOCK2-MFG 3304.96,420 r90 top
J10 "108-0903-001" Cinch_108-0903-001 0,4800 r0 top
J11 "691250610002" FP-691250610002_CONN_TERM_BLOCK2-MFG 250,4040 r270 top
J12 "691250610002" FP-691250610002_CONN_TERM_BLOCK2-MFG 3300,5310 r90 top
J13 "691250610002" FP-691250610002_CONN_TERM_BLOCK2-MFG 3304.96,1573.19 r90 top
J14 "61300211121" WURTH_61300211121 1340,5230 r270 top
J15 "108-0902-001" Cinch_108-0902-001 0,3400 r0 top
J16 "61300211121" WURTH_61300211121 1164.81,5230 r90 top
J17 "108-0903-001" Cinch_108-0903-001 0,2910 r0 top
J18 "691250610002" FP-691250610002_CONN_TERM_BLOCK2-MFG 3300,4050 r90 top
J19 "108-0902-001" Cinch_108-0902-001 0,7135.83 r0 top
J20 "PEC03SAAN" CONN_PEC03SAAN 629.87,6490.99 r270 top
J21 "108-0903-001" Cinch_108-0903-001 0,6650 r0 top
J22 "691250610002" FP-691250610002_CONN_TERM_BLOCK2-MFG 250,5910 r270 top
J23 "691250610002" FP-691250610002_CONN_TERM_BLOCK2-MFG 3300,7200 r90 top
J24 "691250610002" FP-691250610002_CONN_TERM_BLOCK2-MFG 250,2170 r270 top
J25 "61300211121" WURTH_61300211121 1340,7115 r270 top
J26 "61300211121" WURTH_61300211121 1165,7115.82 r90 top
J27 "691250610002" FP-691250610002_CONN_TERM_BLOCK2-MFG 3300,5900 r90 top
J28 "PEC03SAAN" CONN_PEC03SAAN 629.87,2725.72 r270 top
J29 "61300211121" WURTH_61300211121 1340,3350.01 r270 top
J30 "61300211121" WURTH_61300211121 1164.81,3350 r90 top
J31 "691250610002" FP-691250610002_CONN_TERM_BLOCK2-MFG 3304.96,3433.19 r90 top
J32 "691250610002" FP-691250610002_CONN_TERM_BLOCK2-MFG 3304.96,2170 r90 top
Logo1 "CE Mark" CE_Mark_5mm 1782.34,5748.92 r180 bottom
Logo2 "Texas Instruments" TI_Stacked_Overlay_Small 1000.81,6070 r0 top
Logo3 "FCC disclaimer" FCC_disclaimer 2570.8,6430.47 r180 bottom
Logo4 "WEEE logo" WEEE_Minimum 1775.57,7280.32 r180 bottom
LOGO5 "DANGER HIGH VOLTAGE" IEC_HighVoltage_Small 3280,6536.27 r0 top
LOGO6 "DANGER HIGH VOLTAGE" IEC_HighVoltage_Small 3280,4670.85 r0 top
LOGO7 "DANGER HIGH VOLTAGE" IEC_HighVoltage_Small 3280,2805.42 r0 top
LOGO8 "DANGER HIGH VOLTAGE" IEC_HighVoltage_Small 3280,990 r0 top
LOGO9 "CAUTION HOT SURFACE" IEC_HotSurface_Small 2835,997.01 r180 bottom
LOGO10 "CAUTION.  READ USER GUIDE BEFORE USE" IEC_Caution_Small 2834.49,2857.52 r180 bottom
Q1 "UJ4C075033B7S" FP-UJ4C075033B7S_D2PAK7-MFG 2780,5270 r270 top
Q2 "STGD10NC60KDT4" DPAK 2880,743.55 r90 top value="600 V"
Q3 "UJ4C075033B7S" FP-UJ4C075033B7S_D2PAK7-MFG 2780.2,4080 r270 top
Q4 "UJ4C075033B7S" FP-UJ4C075033B7S_D2PAK7-MFG 2700,7220 r0 top
Q5 "UJ4C075033B7S" FP-UJ4C075033B7S_D2PAK7-MFG 2700,3460 r0 top
R1 "ERJ-6GEYJ104V" 0805_HV 1390,840 r0 top value=100k
R2 "ERJ-6GEYJ104V" 0805_HV 1390,750 r0 top value=100k
R3 "ERJ-6GEYJ104V" 0805_HV 1390,660 r0 top value=100k
R4 "WSL060300000ZEA9" FP-WSL060300000ZEA9_0603-MFG 2030,795 r270 top value=0
R5 "CRCW080510R2FKEA" 0805_HV 2172.28,4218.74 r0 top value=10.2
R6 "CRCW080510R2FKEA" 0805_HV 2180,6819.71 r0 top value=10.2
R7 "WSL060300000ZEA9" FP-WSL060300000ZEA9_0603-MFG 2293.1,661.15 r270 top value=0
R8 "ERJ-2RKF2943X" 0402 780,5015 r270 top value=294k
R9 "ERJ-2RKF9092X" 0402 730,5080 r270 top value=90.9k
R10 "CRCW080510R2FKEA" 0805_HV 2425,655 r0 top value=10.2
R11 "ERJ-2RKF2943X" 0402 724.73,1235.04 r270 top value=294k
R12 "ERJ-2RKF9092X" 0402 775,1285 r270 top value=90.9k
R13 "WSL060300000ZEA9" FP-WSL060300000ZEA9_0603-MFG 2370,1160.02 r0 top value=0
R14 "WSL060300000ZEA9" FP-WSL060300000ZEA9_0603-MFG 2370,1030 r0 top value=0
R15 "CRCW060354K9FKEA" 0603 2444.86,1320 r180 top value=54.9k
R16 "WSL060300000ZEA9" FP-WSL060300000ZEA9_0603-MFG 2048.5,4218.74 r270 top value=0
R17 "WSL060300000ZEA9" FP-WSL060300000ZEA9_0603-MFG 2050.01,6795.98 r90 top value=0
R18 "CRCW060320K5FKEA" 0603 2477.12,1220 r90 top value=20.5k
R19 "M55342K12B3E40T" 0603 2477.08,1090 r90 top value=3.40k
R20 "ERJ-6ENF1152V" 0805_HV 2474.57,940 r90 top value=11.5k
R21 "WSL060300000ZEA9" FP-WSL060300000ZEA9_0603-MFG 2040,6430 r270 top value=0
R22 "ERJ-6GEYJ104V" 0805_HV 1390,4600 r0 top value=100k
R23 "ERJ-6GEYJ104V" 0805_HV 1390,4510 r0 top value=100k
R24 "ERJ-6GEYJ104V" 0805_HV 1390,4420 r0 top value=100k
R25 "RC0603JR-072KL" 0603 2328.5,4600.47 r270 top value=2.0k
R26 "CRA2512-FZ-R060ELF" FP-CRA2512-FZ-R060ELF_2512-MFG 2455.78,4520.05 r270 top value=60m
R27 "WSL060300000ZEA9" FP-WSL060300000ZEA9_0603-MFG 2046.54,4556.54 r270 top value=0
R28 "CRA2512-FZ-R060ELF" FP-CRA2512-FZ-R060ELF_2512-MFG 2455.78,4850 r90 top value=60m
R29 "RC0603JR-072KL" 0603 2271.73,4663.38 r270 top value=2.0k
R30 "WSL060300000ZEA9" FP-WSL060300000ZEA9_0603-MFG 2043.84,4952.71 r90 top value=0
R31 "CRCW080510R2FKEA" 0805_HV 2177.4,4952.71 r0 top value=10.2
R32 "ERJ-2RKF2943X" 0402 775,6885 r270 top value=294k
R33 "ERJ-2RKF9092X" 0402 725,6935 r270 top value=90.9k
R34 "ERJ-6GEYJ104V" 0805_HV 1390,2720 r0 top value=100k
R35 "ERJ-6GEYJ104V" 0805_HV 1390,2630 r0 top value=100k
R36 "ERJ-6GEYJ104V" 0805_HV 1390,2540 r0 top value=100k
R37 "WSL060300000ZEA9" FP-WSL060300000ZEA9_0603-MFG 2030,2670.28 r270 top value=0
R38 "ERJ-6GEYJ104V" 0805_HV 1390,6480 r0 top value=100k
R39 "ERJ-6GEYJ104V" 0805_HV 1390,6390 r0 top value=100k
R40 "ERJ-6GEYJ104V" 0805_HV 1390,6300 r0 top value=100k
R41 "RC0603JR-072KL" 0603 2254,6495 r270 top value=2.0k
R42 "RC0603JR-072KL" 0603 2299.93,2720 r270 top value=2.0k
R43 "CRA2512-FZ-R060ELF" FP-CRA2512-FZ-R060ELF_2512-MFG 2725,6495 r90 top value=60m
R44 "RC0603JR-072KL" 0603 2320,6570.94 r270 top value=2.0k
R45 "RC0603JR-072KL" 0603 2240.07,2788.98 r270 top value=2.0k
R46 "WSL060300000ZEA9" FP-WSL060300000ZEA9_0603-MFG 2050.01,3031.65 r90 top value=0
R47 "RC0805FR-070RL" FP-RC0805FR-070RL_0805-MFG 2299.93,2590 r270 top value=0
R48 "CRCW080510R2FKEA" 0805_HV 2180,3030 r0 top value=10.2
R49 "ERJ-2RKF2943X" 0402 780,3120 r270 top value=294k
R50 "ERJ-2RKF9092X" 0402 730,3170 r270 top value=90.9k
R51 "WSL060300000ZEA9" FP-WSL060300000ZEA9_0603-MFG 2372.36,2782.8 r90 top value=0
R52 "ERJ-MS4SF3M0U" FP-ERJ-MS4SF3M0U_2512-MFG 2750,2765 r90 top value=3m
SH-J1 "SNT-100-BK-G" SNT-100-BK-G 2710,8110 r90 top value=1x2
SH-J2 "SNT-100-BK-G" SNT-100-BK-G 5301.37,5064.65 r90 top value=1x2
SH-J3 "SNT-100-BK-G" SNT-100-BK-G 6782.87,3934.65 r90 top value=1x2
SH-J4 "SNT-100-BK-G" SNT-100-BK-G 6677.18,5069.3 r90 top value=1x2
SH-J5 "SNT-100-BK-G" SNT-100-BK-G 6281.21,2279.3 r90 top value=1x2
SH-J6 "SNT-100-BK-G" SNT-100-BK-G 4332.39,2279.3 r90 top value=1x2
SH-J7 "SNT-100-BK-G" SNT-100-BK-G -145,6045 r90 top value=1x2
SH-J8 "SNT-100-BK-G" SNT-100-BK-G -330,6045 r90 top value=1x2
SH-J9 "SNT-100-BK-G" SNT-100-BK-G 2467.64,8110 r90 top value=1x2
SH-J10 "SNT-100-BK-G" SNT-100-BK-G 5318.91,6151.98 r90 top value=1x2
SH-J11 "SNT-100-BK-G" SNT-100-BK-G 5119.79,4221.98 r90 top value=1x2
SH-J12 "SNT-100-BK-G" SNT-100-BK-G 6168.22,3091.98 r90 top value=1x2
TP1 "5012" KSTN-5012_V 1162.14,1675 r0 top
TP2 "EN" Keystone5014 1345,1675 r90 top
TP3 "5012" KSTN-5012_V 920,144.16 r0 top
TP4 "5012" KSTN-5012_V 1390,144.16 r0 top
TP5 "VDDP" Keystone5010 1525,1415 r0 top
TP6 "5011" Keystone5011 1540,365 r0 top
TP7 "5012" KSTN-5012_V 1155,144.16 r0 top
TP8 "EN" Keystone5014 1340,5449.51 r90 top
TP9 "5012" KSTN-5012_V 2209.59,1550 r0 top
TP10 "5012" KSTN-5012_V 2000,5470 r0 top
TP11 "5012" KSTN-5012_V 2252.1,184.16 r0 top
TP12 "5012" KSTN-5012_V 2419.17,1550 r0 top
TP13 "5012" KSTN-5012_V 2000,1550 r0 top
TP14 "VDDP" Keystone5010 1525,5180 r0 top
TP15 "5012" KSTN-5012_V 2115,5370 r0 top
TP16 "5012" KSTN-5012_V 2230,5255 r0 top
TP17 "5012" KSTN-5012_V 2036.59,184.16 r0 top
TP18 "5012" KSTN-5012_V 1165,5450 r0 top
TP19 "5011" Keystone5011 2102.5,470 r0 top
TP20 "5012" KSTN-5012_V 2250,3910 r0 top
TP21 "5012" KSTN-5012_V 2036.59,3910 r0 top
TP22 "5012" KSTN-5012_V 920,3910 r0 top
TP23 "5012" KSTN-5012_V 1155,3910 r0 top
TP24 "5012" KSTN-5012_V 1390,3910 r0 top
TP25 "5011" Keystone5011 2631.26,4676.31 r0 top
TP26 "5011" Keystone5011 1542.55,4183.74 r0 top
TP27 "5012" KSTN-5012_V 1157.14,3570 r0 top
TP28 "EN" Keystone5014 1340,7335 r90 top
TP29 "5012" KSTN-5012_V 2000,7350 r0 top
TP30 "VDDP" Keystone5010 1510,7065.82 r0 top
TP31 "5012" KSTN-5012_V 2150.72,6003.43 r0 top
TP32 "5012" KSTN-5012_V 2397.02,6010.18 r0 top
TP33 "5012" KSTN-5012_V 1165,7333.03 r0 top
TP34 "5012" KSTN-5012_V 2036.59,5790 r0 top
TP35 "5012" KSTN-5012_V 2275,5790 r0 top
TP36 "5012" KSTN-5012_V 920,5780 r0 top
TP37 "5012" KSTN-5012_V 1155,5780 r0 top
TP38 "5012" KSTN-5012_V 1390,5780 r0 top
TP39 "5011" Keystone5011 1535,6005 r0 top
TP40 "5011" Keystone5011 2372.36,6270 r180 top
TP41 "EN" Keystone5014 1340,3570 r90 top
TP42 "5012" KSTN-5012_V 920,2050 r0 top
TP43 "5012" KSTN-5012_V 1390,2050 r0 top
TP44 "VDDP" Keystone5010 1525,3300 r0 top
TP45 "5011" Keystone5011 1540,2300 r0 top
TP46 "5012" KSTN-5012_V 1155,2050 r0 top
TP47 "5012" KSTN-5012_V 2150.72,2254.73 r0 top
TP48 "5012" KSTN-5012_V 2275,2050 r0 top
TP49 "5012" KSTN-5012_V 2397.02,2254.73 r0 top
TP50 "5012" KSTN-5012_V 2000,3560 r0 top
TP51 "5012" KSTN-5012_V 2036.59,2050 r0 top
TP52 "5011" Keystone5011 2527.47,2515 r180 top
U1 "TPSI3133QDVXRQ1" DVX0016A-MFG 1770,900 r0 top
U2 "TPS7A4901DRBR" DRB0008A 563.38,1280 r180 top
U3 "TPS7A4901DRBR" DRB0008A 569.88,5057.2 r180 top
U4 "TPSI3110QDVXRQ1" DVX0016A-MFG 1770,4663.52 r0 top
U5 "TPS7A4901DRBR" DRB0008A 564.88,6927.2 r180 top
U6 "TPSI3100QDVXRQ1" DVX0016A-MFG 1770,2780 r0 top
U7 "TPSI3100QDVXRQ1" DVX0016A-MFG 1770,6545.28 r0 top
U8 "TPS7A4901DRBR" DRB0008A 565.12,3162.8 r180 top
U9 "INA181A1IDBVR" DBV0006A_N 2480,2745.39 r180 top
ZZ1 "This Assembly Note is for PCB labels only" AssemblyNoteLabel 0,7880.32 r0 top
ZZ2 "These assemblies are ESD sensitive, ESD precautions shall be observed." AssemblyNote 0,7780.32 r0 top
ZZ3 "These assemblies must be clean and free from flux and all contaminants. Use of no clean flux is not acceptable." AssemblyNote 0,7680.32 r0 top
ZZ4 "These assemblies must comply with workmanship standards IPC-A-610 Class 2, unless otherwise specified." AssemblyNote 0,7580.32 r0 top

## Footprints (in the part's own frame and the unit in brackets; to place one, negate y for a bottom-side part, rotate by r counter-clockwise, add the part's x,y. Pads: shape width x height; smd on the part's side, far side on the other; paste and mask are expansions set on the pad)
0402 [mm] "0402 from SM-752 data"
  rect 0.8x0.6 smd: 1(-0.6,0) 2(0.6,0)
  silkscreen extent -1.22,-0.52 1.22,0.52, body extent -0.55,-0.3 0.55,0.3, height 0.6
0603 [mm] "0603 from SM-752 data"
  rect 1x0.95 smd: 1(-0.8,0) 2(0.8,0)
  silkscreen extent -1.52,-0.69 1.52,0.69, body extent -0.87,-0.47 0.87,0.47, height 1
0805_HV [mil] "0805 with 30mil clearance between pads"
  rect 50x63 smd: 1(-40,0) 2(40,0)
  silkscreen extent -74,-40 74,40, body extent -43,-29 43,29, height 57
1206 [mm] "1206 from SM-752 data"
  rect 1.3x1.85 smd: 1(-1.45,0) 2(1.45,0)
  silkscreen extent -2.4,-1.21 2.4,1.21, body extent -1.7,-0.9 1.7,0.9, height 1.35
1206_180 [mm] "1206_180"
  rect 1.1x1.6 smd: 1(-1.7,0) 2(1.7,0)
  silkscreen extent -0.9,-1 0.9,1, body extent -1.75,-0.95 1.75,0.95, height 1.8
1210_150 [mm] "1210"
  rect 1.3x2.7 smd: 1(-1.45,0) 2(1.45,0)
  silkscreen extent -2.32,-1.57 2.32,1.57, body extent -1.7,-1.35 1.7,1.35, height 1.5
AssemblyNote [mil] "Assembly Note"
AssemblyNoteLabel [mil] "Assembly Note for PCB Labels"
Bumpon_SJ5003Transparent [mil] "3M Hemispherical Bumpon transparent"
  round 1 on Mech4: 0(0,0)
  silkscreen extent -228,-228 228,228, body extent -219,-219 219,219, height 197
CE_Mark_5mm [mil] "Minimum text height for CE Mark"
  silkscreen extent -138,-98 138,98
Cinch_108-0902-001 [mil] "Banana Jack Insul Nylon Red, TH"
  rrect2% 320x220 smd: 1(185,0)
  body extent -666,-219 272,219, height 232
Cinch_108-0903-001 [mil] "Banana Jack Insul Nylon Black, TH"
  rrect2% 320x220 smd: 1(185,0)
  body extent -666,-219 272,219, height 232
CONN_PEC03SAAN [mm] "SULLINS"
  rect 1.5x1.5 hole 1.016: 1(-2.54,0)
  round 1.5 hole 1.016: 2(0,0) 3(2.54,0)
  silkscreen extent -4.72,-1.27 3.81,1.27, body extent -3.84,-1.3 3.84,1.3, height 8.38
DBV0006A_N [mm] "SOT23, 6-Leads, Body 2.9x1.6mm, Pitch 0.95mm, Lead Span 2.8mm, IPC Medium Density"
  rrect17% 1x0.6 smd: 1(-1.375,0.95) 2(-1.375,0) 3(-1.375,-0.95) 4(1.375,-0.95) 5(1.375,0) 6(1.375,0.95)
  silkscreen extent -1.67,-1.55 0.5,1.55, body extent -1.42,-1.46 1.42,1.46, height 1.12
DPAK [mm] "D-PAK, 3-Pads, Body 6.22x6.73mm (max), TO-252AA using nominal STEP model"
  rrect6% 2.6x1.6 smd: 1(-3.4,2.28) 3(-3.4,-2.28)
  rrect2% 6.2x5.8 smd paste-3: 2(3.4,0)
  body extent -3.86,-3.29 5.84,3.29, height 2.48
DRB0008A [mm] "VSON-8"
  rrect32% 0.6x0.31 smd: 1(-1.4,0.975) 2(-1.4,0.325) 3(-1.4,-0.325) 4(-1.4,-0.975) 5(1.4,-0.975) 6(1.4,-0.325) 7(1.4,0.325) 8(1.4,0.975)
  rrect7% 1.5x1.75 smd paste-0.75: 9(0,0)
  Top Layer region: -0.7,-0.875 -0.49,-0.875 -0.471,-0.879 -0.455,-0.89 -0.444,-0.906 -0.44,-0.925 -0.44,-0.925 -0.44,-1.65 -0.436,-1.669 -0.425,-1.685 -0.409,-1.696 -0.39,-1.7 -0.39,-1.7 -0.26,-1.7 -0.241,-1.696 -0.225,-1.685 -0.214,-1.669 -0.21,-1.65 -0.21,-1.65 -0.21,-0.925 -0.206,-0.906 -0.195,-0.89 -0.179,-0.879 -0.16,-0.875 -0.16,-0.875 0.16,-0.875 0.179,-0.879 0.195,-0.89 0.206,-0.906 0.21,-0.925 0.21,-0.925 0.21,-1.65 0.21,-1.65 0.214,-1.669 0.225,-1.685 0.241,-1.696 0.26,-1.7 0.26,-1.7 0.39,-1.7 0.409,-1.696 0.425,-1.685 0.436,-1.669 0.44,-1.65 0.44,-1.65 0.44,-0.925 0.444,-0.906 0.455,-0.89 0.471,-0.879 0.49,-0.875 0.49,-0.875 0.7,-0.875 0.719,-0.871 0.735,-0.86 0.746,-0.844 0.75,-0.825 0.75,-0.825 0.75,0.825 0.746,0.844 0.735,0.86 0.719,0.871 0.7,0.875 0.7,0.875 0.49,0.875 0.471,0.879 0.455,0.89 0.444,0.906 0.44,0.925 0.44,0.925 0.44,1.65 0.436,1.669 0.425,1.685 0.409,1.696 0.39,1.7 0.39,1.7 0.26,1.7 0.241,1.696 0.225,1.685 0.214,1.669 0.21,1.65 0.21,1.65 0.21,1.65 0.21,0.925 0.206,0.906 0.195,0.89 0.179,0.879 0.16,0.875 0.16,0.875 -0.16,0.875 -0.179,0.879 -0.195,0.89 -0.206,0.906 -0.21,0.925 -0.21,0.925 -0.21,1.65 -0.214,1.669 -0.225,1.685 -0.241,1.696 -0.26,1.7 -0.26,1.7 -0.39,1.7 -0.409,1.696 -0.425,1.685 -0.436,1.669 -0.44,1.65 -0.44,1.65 -0.44,0.925 -0.444,0.906 -0.455,0.89 -0.471,0.879 -0.49,0.875 -0.49,0.875 -0.7,0.875 -0.719,0.871 -0.735,0.86 -0.746,0.844 -0.75,0.825 -0.75,0.825 -0.75,-0.825 -0.746,-0.844 -0.735,-0.86 -0.719,-0.871 -0.7,-0.875
  silkscreen extent -1.73,-1.72 1.73,1.72, body extent -1.5,-1.5 1.5,1.5, height 0.77
DVX0016A-MFG [mm] "Recommended Land Pattern"
  rrect24% 1.7x0.41 smd paste+0 mask+0: 1(-4.85,2.275) 2(-4.85,1.625) 3(-4.85,0.975) 4(-4.85,0.325) 5(-4.85,-0.325) 6(-4.85,-0.975) 7(-4.85,-1.625) 8(-4.85,-2.275) 9(4.85,-2.275) 10(4.85,-1.625) 11(4.85,-0.975) 12(4.85,-0.325) 13(4.85,0.325) 14(4.85,0.975) 15(4.85,1.625) 16(4.85,2.275)
  silkscreen extent -6.37,-2.98 3.5,2.98, body extent -5.8,-3.22 5.8,3.22, height 0.25
FCC_disclaimer [mil]
Fiducial10-20 [mm]
  round 1 smd mask+0.5: 1(0,0)
  Top Layer keep-out circle w1.178: c0,0 r0.5
FP-691250610002_CONN_TERM_BLOCK2-MFG [mm]
  rrect4% 2.3x2.3 hole 1.5 paste-2539.97 mask+0: 1(-2.875,1.65)
  round 2.3 hole 1.5 paste-2539.97 mask+0: 2(3.475,1.65)
  silkscreen extent -7.52,-6.3 6.85,6.3, body extent -6.95,-6.4 6.95,6.4, height 0.25
FP-BBBK00201209252Y00_0805-MFG [mm] "Recommended Land Pattern"
  rrect9% 1.1x1.2 smd paste+0 mask+0: 1(-1.1,0) 2(1.1,0)
  silkscreen extent -0.18,-0.73 0.18,0.73, body extent -1.75,-0.82 1.75,0.82, height 0.25
FP-C3D03060E_TO-252-2-MFG [mm]
  rrect8% 1.3x2.4 smd paste+0 mask+0: 1(-2.39,-5) 2(2.39,-5)
  rrect2% 6.2x6.5 smd paste+0 mask+0: 3(0,2.95)
  silkscreen extent -3.67,-2.22 3.67,4.03, body extent -3.77,-6.3 3.77,6.3, height 0.25
FP-C0603R104K5RAC_0603-IPC_B [mil]
  rrect10% 44.33x37.73 smd paste+0 mask+0: 1(-26.6,0) 2(26.6,0)
  body extent -59,-29 59,29, height 10
FP-CC0603KRX7R7BB102_0603-MFG [mm]
  rrect13% 0.8x0.9 smd paste+0 mask+0: 1(-0.75,0) 2(0.75,0)
  silkscreen extent -0.85,-0.85 0.85,0.85, body extent -1.42,-0.82 1.42,0.82, height 0.25
FP-CGA3E3X7R1E334K080AB_0603-MFG [mm]
  rrect14% 0.7x0.7 smd paste+0 mask+0: 1(-0.7,0) 2(0.7,0)
  silkscreen extent -0.95,-0.73 0.95,0.73, body extent -1.15,-0.65 1.15,0.65, height 0.25
FP-CRA2512-FZ-R060ELF_2512-MFG [mm] "Recommended Land Pattern"
  rrect5% 2.1x4 smd paste+0 mask+0: 1(-3.1,0) 2(3.1,0)
  silkscreen extent -1.67,-1.7 1.67,1.7, body extent -4.25,-2.1 4.25,2.1, height 0.25
FP-ERJ-MS4SF3M0U_2512-MFG [mm]
  rrect4% 2.7x3.4 smd paste+0 mask+0: 1(-2.35,0) 2(2.35,0)
  silkscreen extent -0.62,-1.73 0.62,1.73, body extent -3.8,-1.83 3.8,1.83, height 0.25
FP-PMEG6002EB,115_SOD523-MFG [mm]
  rrect20% 0.5x0.6 smd paste-1000 mask+0: 1(-0.7,0) 2(0.7,0)
  body extent -1.07,-0.6 1.07,0.6, height 0.25
FP-RC0805FR-070RL_0805-MFG [mm]
  rrect11% 0.9x1.2 smd paste+0 mask+0: 1(-1.05,0) 2(1.05,0)
  silkscreen extent -0.22,-0.67 0.22,0.67, body extent -1.6,-0.77 1.6,0.77, height 0.25
FP-UJ4C075033B7S_D2PAK7-MFG [mm]
  rrect11% 0.9x3.9 smd paste-1000 mask+0: 1(-3.81,-8.26) 2(-2.54,-8.26) 3(-1.27,-8.26) 4(0,-8.26) 5(1.27,-8.26) 6(2.54,-8.26) 7(3.81,-8.26)
  round 3.627 smd paste-1000 mask+0: 8(-3.222,1.908)
  Top Layer region: -5.24,6.19 -2,6.19 -2,3.51 2,3.51 2,6.19 5.24,6.19 5.24,-0.11 -5.24,-0.11
  silkscreen extent -5.14,-10.89 5.14,-0.48, body extent -5.34,-10.31 5.34,6.29, height 0.25
FP-WSL060300000ZEA9_0603-MFG [mm]
  rrect10% 1.01x1.01 smd paste+0 mask+0: 1(-0.755,0) 2(0.755,0)
  silkscreen extent -0.89,-0.88 0.89,0.88, body extent -1.36,-0.61 1.36,0.61, height 0.25
IEC_Caution_Small [mil]
  silkscreen extent -107,-93 107,92
IEC_HighVoltage_Small [mil]
  silkscreen extent -107,-88 107,97
IEC_HotSurface_Small [mil]
  silkscreen extent -107,-93 107,92
Keystone5010 [mil] "Keystone Multipurpose loops"
  round 87 hole 63: 1(0,0)
  silkscreen extent -70,-70 70,70, body extent -63,-63 63,62, height 319
Keystone5011 [mil] "Keystone Multipurpose loops"
  round 87 hole 63: 1(0,0)
  silkscreen extent -70,-70 70,70, body extent -63,-63 63,62, height 319
Keystone5014 [mil] "Keystone Multipurpose loops"
  round 87 hole 63: 1(0,0)
  silkscreen extent -70,-70 70,70, body extent -63,-63 63,62, height 319
KSTN-5012_V [mm] "Test Point, Dia 3.17mm"
  round 2.1 hole 1.6: 1(0,0)
  silkscreen extent -1.59,-1.58 1.59,1.58, body extent -1.59,-1.59 1.59,1.59, height 8.13
SNT-100-BK-G [mil] "Samtec STEP model"
  round 1 on Mech3: 0(0,0)
  body extent -100,-50 100,50, height 344
SOD-123 [mm] "On Semi recommended land pattern"
  rect 0.915x1.22 smd: 1(-1.637,0) 2(1.637,0)
  silkscreen extent -2.74,-1.17 2.03,1.17, body extent -1.93,-0.9 1.93,0.9, height 1.35
TI_Stacked_Overlay_Small [mil]
  silkscreen extent -418,-98 418,98
WE-TVSP_DO-214AA_Bidirectional [mm] "Power TVS Diode, 2-Leads. body 4.32x3.62mm"
  rect 2.3x2.3 smd: 1(-1272.25,-1270) 2(-1267.75,-1270)
  silkscreen extent -1272.28,-1271.97 -1267.72,-1268.03, body extent -1272.7,-1271.81 -1267.3,-1268.19, height 2.38
WE-TVSP_DO-214AA_Unidirectional [mm] "Power TVS Diode, 2-Leads. body 4.32x3.62mm"
  rect 2.3x2.3 smd: 1(-2.25,0) 2(2.25,0)
  silkscreen extent -2.28,-1.97 2.28,1.97, body extent -2.7,-1.81 2.7,1.81, height 2.38
WEEE_Minimum [mil] "WEEElie bin"
  silkscreen extent -95,-172 99,104
WURTH_61300211121 [mm] "Header, 2.54mm, 2x1, TH"
  rrect50% 1.65x1.65 hole 1.15: 1(-1.27,0)
  round 1.65 hole 1.15: 2(1.27,0)
  body extent -2.54,-1.27 2.54,1.27, height 8.54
